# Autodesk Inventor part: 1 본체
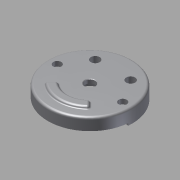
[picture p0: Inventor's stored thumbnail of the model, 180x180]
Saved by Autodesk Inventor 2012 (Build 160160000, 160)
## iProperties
Created: 2015-04
Part Number: 1 본체
Material: Default
Document SubType Name: Modeling
Designer: Owner
Density: 1 g/cm^3
Author: Owner
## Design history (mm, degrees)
sketch "스케치1"
  geometry: C1 r 95 at (0, 0); 1 further point
  constraints: 1 centre point, 1 coincident
  dimensions: "d2" = 190 diameter of C1
extrude "돌출1" new body sketch "스케치1" distance "d3" = 7; taper "d4" = 0 deg
sketch "스케치14"
  geometry: L1 (-82.104, 12)-(-47.117, 12); L2 (47.117, 12)-(82.104, 12); A1 r 95 centre (0, 0) between (-91.763, 24.588) and (91.763, 24.588) reference; A2 r 42 centre (0, 0) between (38.056, 17.769) and (-38.056, 17.769); A3 r 10 centre (47.117, 22) between (38.056, 17.769) and (47.117, 12); A4 r 10 centre (82.104, 22) between (82.104, 12) and (91.763, 24.588); A5 r 10 centre (-47.117, 22) between (-47.117, 12) and (-38.056, 17.769); A6 r 10 centre (-82.104, 22) between (-91.763, 24.588) and (-82.104, 12)
  constraints: 12 point on circle, 12 tangent, 5 centre point, 4 end point, 3 equal radius, 2 horizontal, 1 coincident
  dimensions: "d63" = 84 diameter of A2; "d65" = 20 diameter of A3; "d66" = 12 distance from line of A1.centre L1
extrude "돌출10" join sketch "스케치14" distance "d67" = 7; taper "d68" = 0 deg
sketch "스케치2"
  geometry: L1 (-95, 0)-(95, 0) reference; L2 (95, 0)-(95, -20); L3 (95, -20)-(90, -20); L4 (90, -20)-(90, 0); L5 (0, 0)-(0, -20)
  constraints: 8 end point, 3 perpendicular, 1 horizontal alignment, 1 parallel, 1 point on line
  dimensions: "d5" = 180 diameter of L4 L5; "d6" = 20 distance between parallel lines of L3 L1
revolve "회전1" sketch "스케치2" stored, may be unused: angle "d7" = 90 deg
sketch "스케치13"
  geometry: L1 (0, 0)-(-95, 0); L2 (0, 0)-(-94.638, -8.28); L3 (0, 0)-(95, 0); L4 (0, 0)-(94.638, -8.28); C1 r 90 at (0, 0) reference; C2 r 95 at (0, 0) reference; A1 r 95 centre (0, 0) between (-94.638, -8.28) and (94.638, -8.28); A2 r 90 centre (0, 0) between (-89.658, -7.844) and (89.658, -7.844)
  constraints: 8 end point, 4 point on circle, 2 centre point, 2 coincident, 2 concentric, 2 point on line, 1 collinear, 1 horizontal
  dimensions: "d50" = 5 deg angle of L1 L2; "d51" = 5 deg angle of L4 L3 (= d50); "d52" = 95 distance of L1.start L1.end; "d53" = 95 distance of L1.start L3.end (= d52)
extrude "돌출9" join sketch "스케치13" distance "d54" = 5; taper "d55" = 0 deg
sketch "스케치15"
  geometry: L1 (-47.117, 12)-(-82.104, 12) reference; L2 (-59, -19)-(-59, -14); L3 (-41, -14)-(-41, -19); L4 (41, -19)-(41, -14); L5 (59, -14)-(59, -19); A1 r 90 centre (0, 0) between (-88.811, 14.583) and (88.811, 14.583) reference; A2 r 9 centre (-50, -14) between (-41, -14) and (-59, -14); A3 r 41 centre (0, -19) between (-41, -19) and (41, -19); A4 r 9 centre (50, -14) between (59, -14) and (41, -14); A5 r 59 centre (0, -19) between (-59, -19) and (59, -19)
  constraints: 8 end point, 8 point on circle, 8 tangent, 4 centre point, 4 horizontal alignment, 3 parallel, 1 coincident, 1 perpendicular, 1 vertical alignment
  dimensions: "d69" = 19 distance of A1.centre A3.centre; "d70" = 41 radius of A3; "d71" = 59 radius of A5; "d72" = 5 distance of L2.start L2.end
extrude "돌출11" cut sketch "스케치15" distance "d73" = 7; taper "d74" = 0 deg
sketch "스케치16"
  geometry: C1 r 35 at (0, 0); A1 r 42 centre (0, 0) between (38.056, 17.769) and (-38.056, 17.769) reference
  constraints: 1 centre point, 1 coincident
  dimensions: "d75" = 70 diameter of C1
extrude "돌출12" join sketch "스케치16" distance "d76" = 10; taper "d77" = -10 deg
sketch "스케치17"
  geometry: C1 r 33.237 at (0, 0) reference; C2 r 25 at (0, 0)
  constraints: 1 centre point, 1 coincident
  dimensions: "d78" = 50 diameter of C2
extrude "돌출13" cut sketch "스케치17" distance "d79" = 15; taper "d80" = 0 deg
sketch "스케치18"
  geometry: C1 r 25 at (0, 0) reference; C2 r 11.5 at (0, 0)
  constraints: 1 centre point, 1 coincident
  dimensions: "d81" = 23 diameter of C2
extrude "돌출14" cut sketch "스케치18" stored distance "d82" = 15; taper "d83" = 0 deg
sketch "스케치25"
  geometry: L1 (-47.117, 12)-(-82.104, 12) reference; L2 (-74, 0)-(74, 0); C1 r 35 at (0, 0) reference; C2 r 9 at (-74, 0); C3 r 9 at (74, 0); C4 r 5.5 at (-74, 0); C5 r 5.5 at (74, 0); 1 further point
  constraints: 5 coincident, 4 centre point, 2 end point, 2 equal radius, 1 midpoint, 1 parallel
  dimensions: "d126" = 148 distance of L2.start L2.end; "d127" = 18 diameter of C2; "d128" = 11 diameter of C4
extrude "돌출21" join sketch "스케치25" distance "d129" = 18; taper "d130" = 0 deg
sketch "스케치19"
  geometry: L1 (-74, 0)-(74, 0); C1 r 11.5 at (0, 0) reference; 3 further points
  constraints: 3 coincident, 2 end point, 1 horizontal, 1 midpoint
  dimensions: "d84" = 148 distance of L1.start L1.end
hole "구멍1" sketch "스케치19" at (-74, 0), (74, 0) diameter "d85" = 11; stored, may be unused: countersink angle "d89" = 90 deg, drill point angle "d91" = 0 deg; dims "d86" = 6, "d87" = 18, "d88" = 11, "d90" = 8
sketch "스케치21"
  geometry: L1 (47.117, 12)-(82.104, 12) reference; L2 (-40, 52)-(40, 52); C1 r 15 at (-40, 52); C2 r 15 at (40, 52); A1 r 90 centre (0, 0) between (88.811, 14.583) and (-88.811, 14.583) reference; 1 further point
  constraints: 2 centre point, 2 coincident, 2 end point, 1 equal radius, 1 midpoint, 1 parallel, 1 vertical alignment
  dimensions: "d97" = 52 distance from line of A1.centre L2; "d98" = 80 distance of L2.start L2.end; "d99" = 30 diameter of C1
extrude "돌출16" join sketch "스케치21" distance "d100" = 25; taper "d101" = 0 deg
extrude "돌출17" join sketch "스케치21" distance "d102" = 25; taper "d103" = 0 deg
sketch "스케치22"
  geometry: C1 r 15 at (0, 0) reference; C2 r 10 at (0, 0); C3 r 15 at (80, 0) reference; C4 r 10 at (80, 0); 1 further point
  constraints: 2 centre point, 2 coincident
  dimensions: "d104" = 20 diameter of C2; "d105" = 20 diameter of C4
extrude "돌출18" cut sketch "스케치22" stored distance "d106" = 32; taper "d107" = 0 deg
sketch "스케치23"
  geometry: L1 (6, 13.748)-(6, 8); L2 (6, -8)-(6, -13.748); L3 (-6, -13.748)-(-6, -8); L4 (-6, 8)-(-6, 13.748); A1 r 10 centre (0, 0) between (6, 8) and (6, -8) reference; A2 r 15 centre (0, 0) between (-6, 13.748) and (6, 13.748) reference; 1 further point
  constraints: 8 end point, 8 point on circle, 4 parallel, 2 horizontal alignment, 2 vertical
  dimensions: "d109" = 12 distance between parallel lines of L1 L4; "d110" = 12 distance between parallel lines of L2 L3
extrude "돌출19" cut sketch "스케치23" distance "d111" = 3; taper "d112" = 0 deg
sketch "스케치24"
  geometry: L1 (-13.748, 6)-(-8, 6); L2 (8, 6)-(13.748, 6); L3 (13.748, -6)-(8, -6); L4 (-8, -6)-(-13.748, -6); A1 r 10 centre (0, 0) between (-8, 6) and (8, 6) reference; A2 r 15 centre (0, 0) between (-13.748, 6) and (-13.748, -6) reference; 1 further point
  constraints: 8 end point, 8 point on circle, 4 parallel, 2 horizontal, 2 vertical alignment
  dimensions: "d114" = 12 distance between parallel lines of L2 L3; "d115" = 12 distance between parallel lines of L4 L1
extrude "돌출20" cut sketch "스케치24" distance "d116" = 3; taper "d117" = 0 deg
chamfer "모따기1" distance "d118" = 1; stored, may be unused: second distance "d119" = 2, angle "d120" = 45 deg
fillet "모깎기1" dims "d121" = 3
fillet "모깎기2" dims "d122" = 3
fillet "모깎기3" dims "d123" = 3
fillet "모깎기4" dims "d124" = 3
fillet "모깎기5" dims "d125" = 3
fillet "모깎기6" dims "d131" = 3
chamfer "모따기2" distance "d132" = 1; stored, may be unused: second distance "d133" = 2, angle "d134" = 45 deg
sketch "스케치26"
  geometry: L1 (0, 0)-(-36.062, -36.062); L2 (0, 0)-(36.062, -36.062); L3 (-36.062, -36.062)-(-50.912, -50.912); L4 (36.062, -36.062)-(50.912, -50.912); C1 r 12.5 at (0, 0) reference; A1 r 51 centre (0, 0) between (-36.062, -36.062) and (36.062, -36.062); A2 r 72 centre (0, 0) between (-50.912, -50.912) and (50.912, -50.912)
  constraints: 8 end point, 4 point on circle, 2 centre point, 2 coincident, 2 perpendicular, 1 horizontal alignment
  dimensions: "d136" = 102 diameter of A1; "d137" = 90 deg angle of L2 L1; "d138" = 72 radius of A2
extrude "돌출22" join sketch "스케치26" distance "d139" = 5; taper "d140" = 0 deg
fillet "모깎기7" dims "d141" = 5
fillet "모깎기8" dims "d142" = 5
fillet "모깎기9" dims "d143" = 3
fillet "모깎기10" dims "d144" = 5
fillet "모깎기11" dims "d145" = 1
fillet "모깎기12" dims "d146" = 0.3
node "솔리드1"
other parameters: "d57" = 12, "d64" = 12, "d108" = 12, "d113" = 12, "d135" = 144
